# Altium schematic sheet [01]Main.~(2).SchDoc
size A4; SheetNumber: 1; SheetTotal: 4
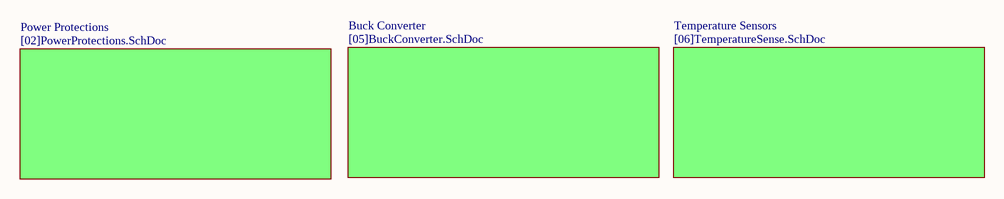
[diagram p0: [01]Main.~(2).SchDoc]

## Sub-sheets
Buck Converter = [05]BuckConverter.SchDoc: no entries
Power Protections = [02]PowerProtections.SchDoc: no entries
Temperature Sensors = [06]TemperatureSense.SchDoc: no entries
